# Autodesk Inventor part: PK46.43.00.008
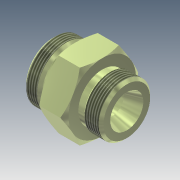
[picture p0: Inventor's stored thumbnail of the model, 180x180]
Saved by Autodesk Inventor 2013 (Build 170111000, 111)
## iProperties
Shininess: 64.0
Length Units: 11269
Angle Units: 11279
Time Units: 11290
Mass Units: 11283
Length Display Precision: 3
Angle Display Precision: 2
Compacted: True
Created: 2002-12
Part Number: PK46.43.00.008
Document SubType Name: Modeling
Designer: GSasha
Material: Steel, Mild
Density: 7.86 g/cm^3
Density: 0.0
Volumn: 0.0
Area: 0.0
PropertySet Name: Model Information
Control State: 0
Master: False
Checked Out: True
Checked Out Date: 2008-10-09
Last Check In Date: 2008-10-09
Author: GSasha
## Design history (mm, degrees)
sketch "Sketch1"
  geometry: L1 (-19.251, 0)-(-19.251, 22); L2 (-19.251, 22)-(-17.251, 24); L3 (-17.251, 24)-(-8.398, 24); L4 (-8.398, 24)-(-6.398, 22); L5 (-6.044, 21.854)-(-2.251, 21.854); L6 (-1.251, 22.854)-(-1.251, 27.5); L7 (-1.251, 27.5)-(2.708, 34.358); L8 (2.708, 34.358)-(16.789, 34.358); L9 (16.789, 34.358)-(20.749, 27.5); L10 (20.749, 27.5)-(20.749, 19.5); L11 (40.749, 19)-(40.749, 0); L12 (40.749, 0)-(-19.251, 0) reference; L13 (-19.251, 9.5)-(28.794, 9.5); L14 (28.794, 9.5)-(40.749, 13.5); L15 (40.749, 19)-(38.749, 21); L16 (38.749, 21)-(27.249, 21); L17 (27.249, 21)-(25.749, 19.5); L18 (25.749, 19.5)-(20.749, 19.5); A1 r 0.5 centre (-6.044, 22.354) between (-6.398, 22) and (-6.044, 21.854); A2 r 1 centre (-2.251, 22.854) between (-2.251, 21.854) and (-1.251, 22.854); 2 further points
  constraints: 36 end point, 9 parallel, 6 point on line, 4 perpendicular, 4 point on circle, 4 tangent, 2 centre point, 2 equal length, 1 horizontal, 1 vertical
  dimensions: "d0" = 2 distance from line of L2.end L1; "d1" = 45 deg angle of L1 L2; "d4" = 5 distance of point (-6.251, 21.854) point (-1.251, 21.854); "d6" = 30 deg angle of L7 L6; "d7" = 30 deg angle of L9 L10; "d9" = 18 distance between parallel lines of L1 L6; "d10" = 60 distance of L11.end L1.start; "d11" = 20 distance between parallel lines of L11 L10; "d12" = 9.5 distance between parallel lines of L12 L13; "d13" = 24 distance between parallel lines of L12 L3; "d14" = 27.5 distance from line of L6.end L12; "d15" = 18.5 deg angle of L14 L12; "d16" = 13.5 distance from line of L14.end L12; "d17" = 0.5 radius of A1; "d18" = 1 radius of A2; "d23" = 45 deg angle of L16 L15 (derived); "d24" = 2 horizontal distance of L11.start L15.end; "d25" = 135 deg angle of L16 L17 (derived); "d26" = 5 distance of L17.end L10.end; "d27" = 21 distance between parallel lines of L16 L12; "d28" = 19.5 distance between parallel lines of L12 L18
revolve "Revolution1" sketch "Sketch1" stored, may be unused: angle "d19" = 90 deg
sketch "Sketch2"
  geometry: L1 (0, 31.754)-(27.5, 15.877); L2 (27.5, 15.877)-(27.5, -15.877); L3 (27.5, -15.877)-(0, -31.754); L4 (0, -31.754)-(-27.5, -15.877); L5 (-27.5, -15.877)-(-27.5, 15.877); L6 (-27.5, 15.877)-(0, 31.754); C1 r 34.358 at (0, 0) reference; 1 further point
  constraints: 12 end point, 1 coincident, 11 other
  dimensions: "d20" = 55 distance between parallel lines of L2 L5
extrude "Extrusion1" cut sketch "Sketch2" stored distance "d21" = 10; taper "d22" = 0 deg
feature "Резьба1" dims "d29" = 10, "d30" = 0
feature "Резьба2" dims "d31" = 10, "d32" = 0
body "Solid1"
